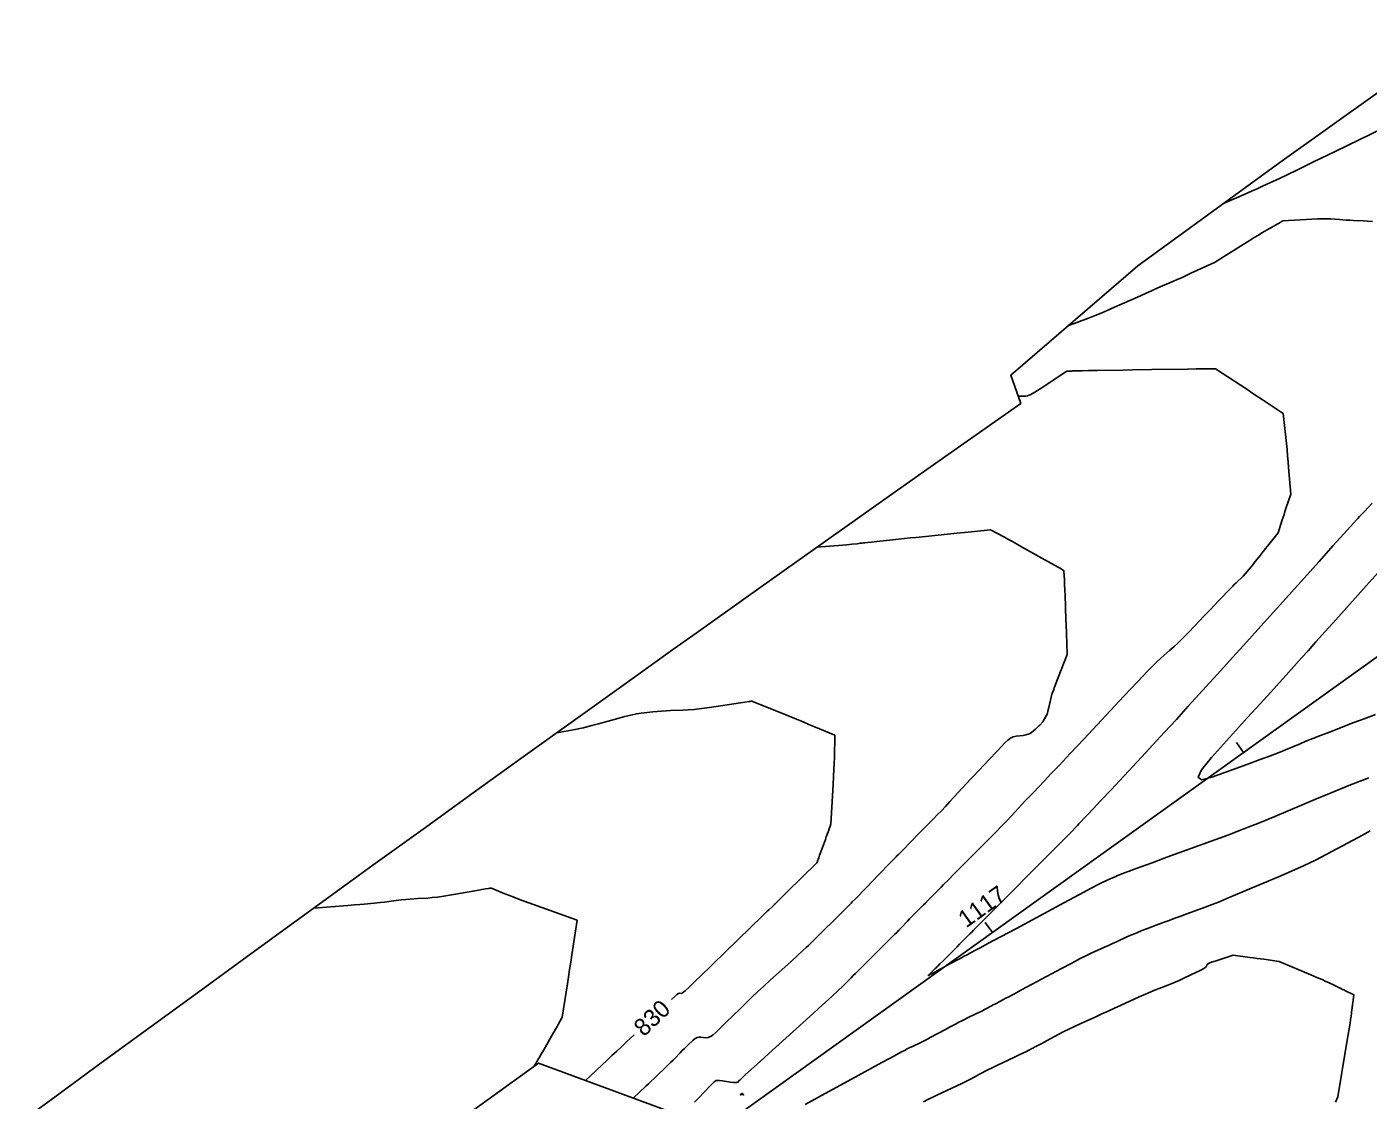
# Model space of a CAD drawing. Extents: x 2079879 to 2092887, y 778083 to 784051.
# Drawn here: x 2083587.5 to 2083804.7, y 780794.9 to 780968.7 of the extents above; entities that cross this region are included whole.
import ezdxf

# ---------------------------------------------------------------- set-up
doc = ezdxf.new("R2010")
doc.units = 0
for name, color, linetype in [('DT_X_Contour_Major', 7, 'Continuous'), ('DT_X_Contour_Minor', 7, 'Continuous'), ('DT_X_TIN_Hull', 7, 'Continuous'), ('GE_X_CL_20', 7, 'Continuous')]:
    doc.layers.add(name, color=color, linetype=linetype)

msp = doc.modelspace()

# ---------------------------------------------------------------- linework, layer by layer
at = {"layer": 'DT_X_Contour_Major'}
for points in [[(2083673.36, 780854.43), (2083676.31, 780854.96), (2083676.82, 780855.05), (2083677.32, 780855.14), (2083677.64, 780855.21), (2083678.2, 780855.36), (2083679.01, 780855.58), (2083680.07, 780855.87), (2083683.23, 780856.75), (2083684.35, 780857.06), (2083685.35, 780857.29), (2083686.23, 780857.47), (2083687, 780857.58), (2083688.87, 780857.8), (2083689.57, 780857.88), (2083690.29, 780857.94), (2083691.02, 780857.98), (2083691.77, 780858.01), (2083693.76, 780858.07), (2083694.59, 780858.12), (2083695.59, 780858.21), (2083696.75, 780858.35), (2083698.07, 780858.53), (2083703.05, 780859.26), (2083704.46, 780859.47), (2083704.64, 780859.5), (2083704.66, 780859.5), (2083704.67, 780859.5), (2083704.68, 780859.5), (2083704.68, 780859.5), (2083704.69, 780859.51), (2083704.72, 780859.51), (2083704.73, 780859.51), (2083704.74, 780859.51), (2083704.76, 780859.52), (2083704.78, 780859.52), (2083704.9, 780859.53), (2083710.93, 780857.1), (2083712.15, 780856.61), (2083713.23, 780856.17), (2083714.16, 780855.78), (2083714.96, 780855.45), (2083718.33, 780854.01), (2083718.27, 780850.34), (2083718.24, 780849.49), (2083718.21, 780848.48), (2083718.15, 780847.33), (2083718.08, 780846.04), (2083717.72, 780839.65), (2083717.67, 780839.53), (2083717.65, 780839.46), (2083717.58, 780839.29), (2083717.49, 780839.02), (2083717.36, 780838.66), (2083716.96, 780837.57), (2083716.82, 780837.16), (2083716.66, 780836.73), (2083716.5, 780836.29), (2083716.34, 780835.84), (2083715.89, 780834.61), (2083715.75, 780834.2), (2083715.63, 780833.89), (2083715.56, 780833.69), (2083715.52, 780833.59), (2083715.41, 780833.36), (2083710.71, 780828.73), (2083709.82, 780827.86), (2083709.18, 780827.23), (2083708.79, 780826.83), (2083708.64, 780826.68), (2083708.55, 780826.6), (2083708.5, 780826.55), (2083708.42, 780826.47), (2083708.29, 780826.36), (2083708.13, 780826.21), (2083707.65, 780825.78), (2083707.36, 780825.5), (2083706.84, 780825), (2083706.09, 780824.27), (2083705.11, 780823.32), (2083702.2, 780820.47), (2083701.13, 780819.42), (2083700.09, 780818.41), (2083699.09, 780817.44), (2083698.13, 780816.5), (2083695.6, 780814.04), (2083694.76, 780813.23), (2083694.13, 780812.66), (2083693.71, 780812.33), (2083693.5, 780812.23), (2083693.22, 780812.27), (2083693.06, 780812.22), (2083692.79, 780812.05), (2083692.42, 780811.74), (2083691.94, 780811.31), (2083691.93, 780811.31)], [(2083685.84, 780805.52), (2083684.69, 780804.44), (2083683.86, 780803.65), (2083683.05, 780802.89), (2083682.26, 780802.15), (2083681.5, 780801.43), (2083677.97, 780798.12)]]:
    msp.add_lwpolyline(points, dxfattribs=at)
at = {"layer": 'DT_X_Contour_Minor'}
for points in [[(2083781.24, 780940.11), (2083785.08, 780941.78), (2083785.9, 780942.14), (2083786.7, 780942.49), (2083787.49, 780942.85), (2083788.27, 780943.21), (2083790.31, 780944.15), (2083791.45, 780944.69), (2083793.34, 780945.6), (2083795.96, 780946.87), (2083799.33, 780948.51), (2083816.79, 780957)], [(2083756.09, 780920.29), (2083759.42, 780921.53), (2083760.21, 780921.84), (2083761.18, 780922.24), (2083762.32, 780922.73), (2083763.62, 780923.3), (2083767.33, 780924.95), (2083768.62, 780925.53), (2083769.73, 780926.02), (2083770.65, 780926.42), (2083771.39, 780926.75), (2083773.09, 780927.49), (2083773.75, 780927.78), (2083774.46, 780928.09), (2083775.21, 780928.43), (2083776, 780928.8), (2083779.82, 780930.56), (2083784.47, 780933.48), (2083785.4, 780934.07), (2083786.22, 780934.57), (2083786.91, 780934.99), (2083787.48, 780935.33), (2083788.84, 780936.11), (2083789.3, 780936.38), (2083789.68, 780936.6), (2083789.96, 780936.77), (2083790.16, 780936.88), (2083790.86, 780937.3), (2083795.55, 780937.56), (2083796.5, 780937.6), (2083797.33, 780937.62), (2083798.04, 780937.62), (2083798.62, 780937.6), (2083800.03, 780937.5), (2083800.57, 780937.46), (2083801.13, 780937.42), (2083801.71, 780937.39), (2083802.31, 780937.36), (2083803.93, 780937.28), (2083804.59, 780937.24), (2083805.37, 780937.18)], [(2083748.03, 780908.91), (2083749.22, 780908.89), (2083749.56, 780908.96), (2083750.06, 780909.18), (2083750.74, 780909.56), (2083751.58, 780910.1), (2083755.9, 780912.94), (2083756.59, 780912.98), (2083756.74, 780912.98), (2083756.87, 780912.99), (2083757, 780913), (2083757.13, 780913), (2083757.44, 780913.01), (2083757.74, 780913.01), (2083758.4, 780913.02), (2083759.42, 780913.04), (2083760.8, 780913.06), (2083764.96, 780913.13), (2083766.52, 780913.16), (2083769.66, 780913.21), (2083775.45, 780913.3), (2083776.85, 780913.33), (2083777.87, 780913.34), (2083778.53, 780913.35), (2083778.81, 780913.36), (2083779.06, 780913.36), (2083779.16, 780913.36), (2083779.26, 780913.36), (2083779.36, 780913.36), (2083779.46, 780913.36), (2083779.95, 780913.36), (2083785.02, 780910.02), (2083786.04, 780909.35), (2083786.93, 780908.76), (2083787.69, 780908.26), (2083788.31, 780907.85), (2083790.92, 780906.13), (2083791.44, 780901.27), (2083791.55, 780900.25), (2083791.64, 780899.25), (2083791.73, 780898.28), (2083791.81, 780897.35), (2083792.17, 780893.05), (2083791.38, 780890.74), (2083791.21, 780890.25), (2083791.06, 780889.78), (2083790.9, 780889.32), (2083790.76, 780888.87), (2083790.11, 780886.81), (2083788.38, 780884.64), (2083788.03, 780884.2), (2083787.73, 780883.81), (2083787.46, 780883.48), (2083787.23, 780883.19), (2083786.68, 780882.49), (2083786.46, 780882.21), (2083786.23, 780881.93), (2083785.99, 780881.62), (2083785.72, 780881.3), (2083784.46, 780879.77), (2083783.33, 780878.71), (2083783.07, 780878.46), (2083782.77, 780878.15), (2083782.42, 780877.8), (2083782.03, 780877.4), (2083780.95, 780876.26), (2083780.47, 780875.76), (2083779.85, 780875.11), (2083779.1, 780874.33), (2083778.21, 780873.4), (2083775.64, 780870.73), (2083774.73, 780869.8), (2083773.92, 780868.99), (2083773.21, 780868.32), (2083772.6, 780867.77), (2083771.1, 780866.48), (2083770.31, 780865.74), (2083769.04, 780864.46), (2083767.32, 780862.66), (2083765.12, 780860.33), (2083758.64, 780853.41), (2083756.43, 780851.04), (2083754.64, 780849.14), (2083753.28, 780847.7), (2083752.35, 780846.71), (2083750.44, 780844.71), (2083749.75, 780843.99), (2083749.13, 780843.33), (2083748.58, 780842.74), (2083748.09, 780842.22), (2083746.88, 780840.9), (2083746.29, 780840.28), (2083745.45, 780839.41), (2083744.35, 780838.29), (2083742.99, 780836.93), (2083739.02, 780832.95), (2083737.69, 780831.61), (2083736.67, 780830.58), (2083735.95, 780829.85), (2083735.54, 780829.44), (2083734.87, 780828.75), (2083734.63, 780828.5), (2083734.4, 780828.26), (2083734.18, 780828.04), (2083733.98, 780827.84), (2083733.46, 780827.32), (2083733, 780826.86), (2083732.71, 780826.57), (2083732.4, 780826.25), (2083731.5, 780825.36), (2083731.16, 780825.02), (2083730.81, 780824.66), (2083730.46, 780824.29), (2083730.09, 780823.91), (2083729.1, 780822.87), (2083728.73, 780822.49), (2083728.36, 780822.11), (2083728, 780821.74), (2083727.64, 780821.38), (2083726.68, 780820.43), (2083726.32, 780820.07), (2083725.96, 780819.7), (2083725.59, 780819.33), (2083725.22, 780818.96), (2083724.23, 780817.97), (2083723.86, 780817.61), (2083723.51, 780817.26), (2083723.17, 780816.92), (2083722.85, 780816.6), (2083722, 780815.77), (2083721.68, 780815.45), (2083721.34, 780815.11), (2083720.98, 780814.75), (2083720.6, 780814.38), (2083719.57, 780813.35), (2083718.95, 780812.75), (2083717.86, 780811.75), (2083716.31, 780810.32), (2083714.28, 780808.48), (2083708.25, 780803.03), (2083706.26, 780801.22), (2083704.81, 780799.91), (2083703.9, 780799.08), (2083703.53, 780798.74), (2083703.26, 780798.48), (2083703.16, 780798.38), (2083703.06, 780798.29), (2083702.97, 780798.2), (2083702.88, 780798.11), (2083702.65, 780797.88), (2083702.51, 780797.82), (2083702.27, 780797.79), (2083701.93, 780797.81), (2083701.48, 780797.87), (2083700.15, 780798.07), (2083699.7, 780798.12), (2083699.35, 780798.14), (2083699.1, 780798.11), (2083698.95, 780798.03), (2083698.68, 780797.78), (2083698.52, 780797.63), (2083698.27, 780797.37), (2083697.91, 780797), (2083697.46, 780796.52), (2083696.1, 780795.09), (2083695.64, 780794.6)], [(2083805.34, 780891.57), (2083804.08, 780890.26), (2083803.64, 780889.81), (2083803.28, 780889.43), (2083802.99, 780889.12), (2083802.77, 780888.88), (2083802.29, 780888.34), (2083801.81, 780887.8), (2083800.72, 780886.6), (2083799.04, 780884.72), (2083796.75, 780882.17), (2083789.83, 780874.48), (2083787.32, 780871.69), (2083784.97, 780869.08), (2083782.78, 780866.66), (2083780.76, 780864.42), (2083775.57, 780858.7), (2083773.64, 780856.58), (2083771.73, 780854.5), (2083769.84, 780852.46), (2083767.98, 780850.47), (2083763.06, 780845.2), (2083761.41, 780843.44), (2083760.15, 780842.1), (2083759.29, 780841.18), (2083758.82, 780840.69), (2083758.1, 780839.94), (2083757.85, 780839.67), (2083757.61, 780839.42), (2083757.41, 780839.2), (2083757.22, 780839), (2083756.77, 780838.51), (2083756.32, 780838.04), (2083755.32, 780837.03), (2083753.76, 780835.46), (2083751.65, 780833.35), (2083745.29, 780826.97), (2083743.2, 780824.87), (2083741.69, 780823.36), (2083740.78, 780822.44), (2083740.45, 780822.11), (2083740.36, 780822.01), (2083740.29, 780821.94), (2083740.15, 780821.81), (2083739.95, 780821.6), (2083739.68, 780821.33), (2083738.86, 780820.51), (2083738.53, 780820.18), (2083738.14, 780819.79), (2083737.7, 780819.35), (2083737.21, 780818.85), (2083735.81, 780817.46), (2083735.35, 780817), (2083735.02, 780816.66), (2083734.82, 780816.46), (2083734.74, 780816.39), (2083734.71, 780816.36), (2083734.68, 780816.32), (2083734.61, 780816.25), (2083734.49, 780816.13), (2083734.33, 780815.97), (2083733.48, 780815.12), (2083734.54, 780815.69), (2083734.73, 780815.8), (2083734.88, 780815.88), (2083734.97, 780815.93), (2083735.02, 780815.95), (2083735.05, 780815.97), (2083735.15, 780816.02), (2083735.4, 780816.15), (2083735.81, 780816.37), (2083736.38, 780816.68), (2083738.12, 780817.61), (2083738.74, 780817.94), (2083739.29, 780818.24), (2083739.77, 780818.49), (2083740.19, 780818.72), (2083741.2, 780819.26), (2083741.89, 780819.63), (2083743.21, 780820.34), (2083745.16, 780821.38), (2083747.73, 780822.76), (2083755.43, 780826.89), (2083757.98, 780828.25), (2083759.86, 780829.26), (2083761.09, 780829.9), (2083761.64, 780830.18), (2083762.23, 780830.45), (2083762.46, 780830.55), (2083762.69, 780830.65), (2083762.93, 780830.76), (2083763.18, 780830.88), (2083763.85, 780831.18), (2083764.11, 780831.3), (2083764.41, 780831.42), (2083764.72, 780831.55), (2083765.07, 780831.68), (2083766.02, 780832.04), (2083766.67, 780832.28), (2083767.9, 780832.73), (2083769.71, 780833.39), (2083772.11, 780834.26), (2083779.29, 780836.87), (2083781.95, 780837.85), (2083784.55, 780838.85), (2083787.09, 780839.86), (2083789.56, 780840.88), (2083796.07, 780843.61), (2083798.67, 780844.69), (2083801.57, 780845.86), (2083804.79, 780847.12)], [(2083715.45, 780884.44), (2083718.95, 780884.74), (2083719.65, 780884.8), (2083720.24, 780884.85), (2083720.72, 780884.9), (2083721.09, 780884.93), (2083721.94, 780885.03), (2083722.23, 780885.06), (2083722.46, 780885.09), (2083722.64, 780885.11), (2083722.76, 780885.12), (2083723.01, 780885.15), (2083723.22, 780885.18), (2083723.63, 780885.22), (2083724.27, 780885.29), (2083725.12, 780885.38), (2083727.68, 780885.65), (2083728.64, 780885.76), (2083729.6, 780885.86), (2083730.56, 780885.95), (2083731.53, 780886.05), (2083738.11, 780886.71), (2083739.95, 780886.89), (2083743.53, 780887.25), (2083745.81, 780886.06), (2083746.35, 780885.77), (2083746.99, 780885.43), (2083747.74, 780885.01), (2083748.59, 780884.54), (2083753.31, 780881.9), (2083754.02, 780881.5), (2083754.27, 780881.36), (2083754.48, 780881.24), (2083754.67, 780881.13), (2083754.82, 780881.04), (2083755.44, 780880.65), (2083755.48, 780879.85), (2083755.49, 780879.65), (2083755.5, 780879.37), (2083755.54, 780878.59), (2083755.59, 780877.35), (2083755.61, 780876.82), (2083755.64, 780876.15), (2083755.67, 780875.34), (2083755.71, 780874.4), (2083755.8, 780871.7), (2083755.83, 780870.77), (2083755.86, 780869.99), (2083755.88, 780869.37), (2083755.89, 780868.9), (2083755.94, 780867.07), (2083754.52, 780863.35), (2083754.25, 780862.64), (2083754.04, 780862.08), (2083753.88, 780861.67), (2083753.79, 780861.43), (2083753.5, 780860.65), (2083752.99, 780858.53), (2083752.89, 780858.13), (2083752.83, 780857.85), (2083752.79, 780857.67), (2083752.77, 780857.61), (2083752.77, 780857.59), (2083752.75, 780857.56), (2083752.71, 780857.48), (2083752.64, 780857.35), (2083752.54, 780857.16), (2083752.03, 780856.19), (2083751.51, 780855.65), (2083751.39, 780855.52), (2083751.23, 780855.38), (2083751.04, 780855.21), (2083750.83, 780855.02), (2083750.21, 780854.49), (2083749.95, 780854.31), (2083749.64, 780854.17), (2083749.28, 780854.06), (2083748.86, 780853.99), (2083747.68, 780853.85), (2083747.24, 780853.75), (2083746.79, 780853.53), (2083746.34, 780853.21), (2083745.89, 780852.78), (2083744.67, 780851.48), (2083744.2, 780850.99), (2083743.73, 780850.49), (2083743.25, 780849.98), (2083742.76, 780849.47), (2083741.44, 780848.08), (2083740.91, 780847.52), (2083740.32, 780846.89), (2083739.67, 780846.2), (2083738.96, 780845.43), (2083736.99, 780843.29), (2083736.27, 780842.51), (2083735.59, 780841.79), (2083734.94, 780841.12), (2083734.33, 780840.5), (2083732.76, 780838.92), (2083732.18, 780838.35), (2083731.64, 780837.8), (2083731.12, 780837.27), (2083730.64, 780836.77), (2083729.39, 780835.49), (2083728.97, 780835.05), (2083728.64, 780834.72), (2083728.41, 780834.48), (2083728.28, 780834.35), (2083728.05, 780834.12), (2083727.96, 780834.03), (2083727.85, 780833.92), (2083727.73, 780833.8), (2083727.59, 780833.66), (2083727.2, 780833.26), (2083726.98, 780833.04), (2083726.61, 780832.66), (2083726.1, 780832.13), (2083725.44, 780831.44), (2083723.48, 780829.39), (2083722.82, 780828.7), (2083722.29, 780828.15), (2083721.91, 780827.76), (2083721.66, 780827.5), (2083721.18, 780827.03), (2083721, 780826.85), (2083720.82, 780826.67), (2083720.64, 780826.48), (2083720.45, 780826.3), (2083719.96, 780825.8), (2083719.71, 780825.56), (2083719.34, 780825.19), (2083718.84, 780824.7), (2083718.22, 780824.09), (2083716.4, 780822.29), (2083715.78, 780821.68), (2083715.27, 780821.18), (2083714.89, 780820.8), (2083714.62, 780820.53), (2083714.06, 780819.97), (2083713.73, 780819.65), (2083713.14, 780819.11), (2083712.3, 780818.34), (2083711.21, 780817.35), (2083707.95, 780814.4), (2083706.81, 780813.36), (2083705.82, 780812.46), (2083704.99, 780811.68), (2083704.32, 780811.03), (2083702.73, 780809.47), (2083702.14, 780808.9), (2083701.58, 780808.35), (2083701.03, 780807.82), (2083700.51, 780807.3), (2083699.13, 780805.96), (2083698.64, 780805.53), (2083698.2, 780805.23), (2083697.82, 780805.07), (2083697.49, 780805.05), (2083696.68, 780805.17), (2083696.38, 780805.17), (2083696.07, 780805.09), (2083695.76, 780804.93), (2083695.44, 780804.67), (2083694.59, 780803.89), (2083694.27, 780803.59), (2083693.96, 780803.28), (2083693.64, 780802.96), (2083693.32, 780802.63), (2083692.48, 780801.75), (2083692.15, 780801.4), (2083691.77, 780801.02), (2083691.34, 780800.6), (2083690.88, 780800.16), (2083689.58, 780798.93), (2083689.1, 780798.48), (2083688.63, 780798.04), (2083688.18, 780797.61), (2083687.73, 780797.2), (2083685.69, 780795.28)], [(2083806.32, 780880.37), (2083804.35, 780878.2), (2083799.45, 780872.72), (2083797.72, 780870.79), (2083796.22, 780869.12), (2083794.95, 780867.7), (2083793.9, 780866.53), (2083791.41, 780863.76), (2083790.32, 780862.55), (2083788.92, 780861), (2083787.2, 780859.1), (2083785.17, 780856.87), (2083779.34, 780850.44), (2083777.7, 780848.43), (2083777.16, 780847.22), (2083777.71, 780846.82), (2083779.35, 780847.21), (2083785.18, 780849.33), (2083787.2, 780850.07), (2083788.9, 780850.71), (2083790.27, 780851.23), (2083791.31, 780851.66), (2083793.66, 780852.64), (2083794.62, 780853.04), (2083795.73, 780853.48), (2083796.99, 780853.98), (2083798.41, 780854.53), (2083802.39, 780856.06), (2083804.01, 780856.68), (2083805.86, 780857.39)], [(2083805.02, 780838.53), (2083803.77, 780837.87), (2083802.26, 780837.06), (2083797.88, 780834.71), (2083796.16, 780833.82), (2083794.3, 780832.92), (2083792.3, 780832.01), (2083790.15, 780831.08), (2083784.23, 780828.59), (2083782.17, 780827.73), (2083780.43, 780827.02), (2083778.99, 780826.45), (2083777.88, 780826.03), (2083775.31, 780825.1), (2083774.35, 780824.75), (2083773.4, 780824.4), (2083772.45, 780824.04), (2083771.5, 780823.69), (2083768.97, 780822.74), (2083768.05, 780822.39), (2083767.21, 780822.05), (2083766.43, 780821.73), (2083765.73, 780821.42), (2083763.94, 780820.6), (2083763.28, 780820.3), (2083762.64, 780820.01), (2083762.02, 780819.72), (2083761.42, 780819.45), (2083759.85, 780818.74), (2083759.1, 780818.39), (2083758.05, 780817.86), (2083756.69, 780817.15), (2083755.03, 780816.26), (2083750.17, 780813.66), (2083748.55, 780812.79), (2083747.32, 780812.13), (2083746.49, 780811.68), (2083746.05, 780811.45), (2083745.41, 780811.11), (2083745.15, 780810.97), (2083744.85, 780810.8), (2083744.5, 780810.62), (2083744.11, 780810.41), (2083743.02, 780809.82), (2083742.59, 780809.6), (2083742.15, 780809.37), (2083741.68, 780809.14), (2083741.19, 780808.9), (2083739.85, 780808.27), (2083739.36, 780808.03), (2083738.88, 780807.8), (2083738.42, 780807.56), (2083737.97, 780807.32), (2083736.8, 780806.69), (2083736.36, 780806.45), (2083735.92, 780806.21), (2083735.47, 780805.97), (2083735.01, 780805.72), (2083733.8, 780805.07), (2083733.34, 780804.83), (2083732.9, 780804.6), (2083732.47, 780804.38), (2083732.05, 780804.18), (2083730.94, 780803.66), (2083730.51, 780803.45), (2083730.08, 780803.24), (2083729.62, 780803), (2083729.16, 780802.75), (2083727.89, 780802.06), (2083727.18, 780801.67), (2083725.98, 780801.02), (2083724.3, 780800.11), (2083722.13, 780798.93), (2083715.72, 780795.44), (2083713.56, 780794.26)], [(2083634, 780826.04), (2083639.49, 780826.46), (2083640.57, 780826.55), (2083641.47, 780826.62), (2083642.17, 780826.68), (2083642.69, 780826.72), (2083643.8, 780826.83), (2083644.27, 780826.88), (2083644.81, 780826.94), (2083645.44, 780827.01), (2083646.15, 780827.1), (2083648.16, 780827.35), (2083648.9, 780827.44), (2083649.59, 780827.51), (2083650.25, 780827.56), (2083650.86, 780827.6), (2083652.45, 780827.67), (2083653.14, 780827.73), (2083654, 780827.83), (2083655.05, 780827.99), (2083656.27, 780828.19), (2083659.78, 780828.8), (2083660.94, 780829), (2083661.78, 780829.14), (2083662.31, 780829.23), (2083662.52, 780829.27), (2083662.78, 780829.29), (2083664.67, 780828.47), (2083665.23, 780828.24), (2083666.11, 780827.9), (2083667.31, 780827.45), (2083668.82, 780826.9), (2083676.61, 780824.06), (2083675.78, 780818.46), (2083675.6, 780817.27), (2083675.42, 780816.08), (2083675.24, 780814.92), (2083675.06, 780813.76), (2083674.2, 780808.4), (2083673.55, 780807.2), (2083673.38, 780806.88), (2083673.15, 780806.46), (2083672.85, 780805.94), (2083672.49, 780805.3), (2083671.43, 780803.46), (2083671.07, 780802.84), (2083670.78, 780802.34), (2083670.57, 780801.97), (2083670.43, 780801.73), (2083670.15, 780801.27), (2083670.06, 780801.1), (2083669.98, 780800.97), (2083669.91, 780800.86), (2083669.87, 780800.78), (2083669.7, 780800.45)], [(2083799.38, 780794.63), (2083799.75, 780795.49), (2083801.14, 780803.68), (2083801.41, 780805.26), (2083801.61, 780806.5), (2083801.75, 780807.39), (2083801.83, 780807.93), (2083801.96, 780808.92), (2083802, 780809.25), (2083802.03, 780809.51), (2083802.06, 780809.69), (2083802.07, 780809.79), (2083802.1, 780809.98), (2083802.12, 780810.07), (2083802.14, 780810.22), (2083802.16, 780810.42), (2083802.2, 780810.68), (2083802.36, 780812.01), (2083801.03, 780812.65), (2083800.77, 780812.78), (2083800.55, 780812.88), (2083800.39, 780812.96), (2083800.27, 780813.02), (2083800.02, 780813.13), (2083799.9, 780813.19), (2083799.71, 780813.28), (2083799.47, 780813.4), (2083799.16, 780813.55), (2083798.27, 780813.98), (2083797.84, 780814.18), (2083797.22, 780814.46), (2083796.4, 780814.81), (2083795.4, 780815.24), (2083790.28, 780817.42), (2083787.79, 780817.75), (2083787.25, 780817.83), (2083786.7, 780817.9), (2083786.13, 780817.97), (2083785.55, 780818.05), (2083782.83, 780818.41), (2083779.89, 780817.46), (2083779.34, 780817.27), (2083778.94, 780817.1), (2083778.68, 780816.96), (2083778.58, 780816.85), (2083778.5, 780816.59), (2083778.38, 780816.46), (2083778.07, 780816.26), (2083777.58, 780815.99), (2083776.9, 780815.66), (2083774.84, 780814.69), (2083774.1, 780814.34), (2083773.42, 780814.04), (2083772.8, 780813.78), (2083772.24, 780813.56), (2083770.84, 780813.04), (2083770.24, 780812.8), (2083769.5, 780812.49), (2083768.62, 780812.11), (2083767.61, 780811.65), (2083764.7, 780810.32), (2083763.63, 780809.83), (2083762.59, 780809.36), (2083761.58, 780808.9), (2083760.61, 780808.46), (2083758.06, 780807.31), (2083757.12, 780806.88), (2083756.24, 780806.46), (2083755.41, 780806.04), (2083754.63, 780805.64), (2083752.62, 780804.56), (2083751.94, 780804.19), (2083751.43, 780803.92), (2083751.09, 780803.74), (2083750.91, 780803.64), (2083750.64, 780803.5), (2083750.53, 780803.44), (2083750.41, 780803.37), (2083750.26, 780803.29), (2083750.1, 780803.21), (2083749.65, 780802.96), (2083749.37, 780802.83), (2083748.9, 780802.59), (2083748.21, 780802.26), (2083747.33, 780801.84), (2083744.69, 780800.59), (2083743.8, 780800.17), (2083743.1, 780799.83), (2083742.6, 780799.59), (2083742.3, 780799.43), (2083741.74, 780799.13), (2083741.53, 780799.02), (2083741.32, 780798.9), (2083741.11, 780798.79), (2083740.89, 780798.67), (2083740.31, 780798.36), (2083740.01, 780798.2), (2083739.54, 780797.97), (2083738.89, 780797.66), (2083738.08, 780797.28), (2083735.68, 780796.15), (2083734.86, 780795.76), (2083734.21, 780795.45), (2083733.71, 780795.21), (2083733.38, 780795.03), (2083732.72, 780794.67)], [(2083703.1, 780795.89), (2083703.11, 780795.9), (2083703.13, 780795.92), (2083703.16, 780795.94), (2083703.19, 780795.96), (2083703.29, 780796.02), (2083703.33, 780796.03), (2083703.36, 780796.03), (2083703.39, 780796.02), (2083703.43, 780795.99), (2083703.51, 780795.9), (2083703.53, 780795.87), (2083703.55, 780795.84), (2083703.56, 780795.82), (2083703.56, 780795.81), (2083703.55, 780795.77), (2083703.44, 780795.88), (2083703.41, 780795.89), (2083703.38, 780795.9), (2083703.35, 780795.9), (2083703.31, 780795.89), (2083703.21, 780795.85), (2083703.18, 780795.84), (2083703.15, 780795.83), (2083703.13, 780795.82), (2083703.11, 780795.82), (2083703.04, 780795.81), (2083703.1, 780795.89)]]:
    msp.add_lwpolyline(points, dxfattribs=at)
at = {"layer": 'DT_X_TIN_Hull'}
for points in [[(2083815.06, 780964.33), (2083790.38, 780946.76), (2083767.41, 780930.03), (2083746.84, 780912.33), (2083748.45, 780907.72), (2083744.86, 780905.19), (2083736.68, 780899.44), (2083728.5, 780893.68), (2083720.34, 780887.91), (2083712.18, 780882.13), (2083704.02, 780876.34), (2083695.88, 780870.54), (2083692.3, 780867.99), (2083684.17, 780862.18), (2083676.03, 780856.36), (2083667.91, 780850.53), (2083659.79, 780844.69), (2083651.68, 780838.84), (2083643.57, 780832.98), (2083640.02, 780830.41), (2083631.92, 780824.54), (2083623.83, 780818.66), (2083615.75, 780812.77), (2083607.67, 780806.87), (2083599.6, 780800.97), (2083591.54, 780795.05), (2083588, 780792.45)], [(2083654.14, 780789.21), (2083662.25, 780795.07), (2083670.35, 780800.92), (2083696.28, 780791.39)]]:
    msp.add_lwpolyline(points, dxfattribs=at)
at = {"layer": 'GE_X_CL_20'}
for p, q in [((2079923.52, 778084.44), (2085691.45, 782217.74)), ((2083784.52, 780851.23), (2083783.36, 780852.86)), ((2083743.88, 780822.11), (2083742.71, 780823.73))]:
    msp.add_line(p, q, dxfattribs=at)

# ---------------------------------------------------------------- texts
at = {"layer": 'DT_X_Contour_Major'}
msp.add_text('830', height=2.8, rotation=43.5379, dxfattribs=at).set_placement((2083687.43, 780805.11))
at = {"layer": 'GE_X_CL_20'}
msp.add_text('1117', height=2.8, rotation=35.6254, dxfattribs=at).set_placement((2083739.6, 780822.73))

doc.saveas('drawing.dxf')
